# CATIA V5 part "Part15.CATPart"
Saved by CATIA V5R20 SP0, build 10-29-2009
Part number: bielle_2_hab
Bounding box of the stored display mesh (mm): x 0.1 to 0.15, y 0.877 to 2.164, z 2.08 to 2.712
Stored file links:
  D:\Dropbox\IAO_2012\IAO_2012_718_ccascaro\ccascaro\Part15.CATPart
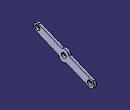
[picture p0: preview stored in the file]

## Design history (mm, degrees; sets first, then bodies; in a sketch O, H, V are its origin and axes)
Body1 (main body)
  Sketch1 on yz-plane, origin (0, 0, 0), H (0, 1, 0), V (0, 0, 1)
    point P1 (1.4759, 2.469)
    point P3 (1.4892, 2.3124)
    circle A1 centre (2.0719, 2.1705) radius 0.05
    arc A2 centre (2.073, 2.1711) radius 0.0914 from (2.1359, 2.2375) to (2.0105, 2.1045) cw
    line L1 (2.1359, 2.2375) -> (1.6294, 2.4448)
    line L2 (0.9853, 2.7085) -> (1.4759, 2.5077)
    point P10 (1.4759, 2.5077)
    arc A3 centre (1.5344, 2.4317) radius 0.0959 from (1.6294, 2.4448) to (1.4759, 2.5077) ccw
    line L3 (2.0102, 2.1048) -> (1.5666, 2.2879)
    point P13 (2.0102, 2.1048)
    line L4 (1.4111, 2.3495) -> (0.922, 2.5538)
    circle A4 centre (1.5199, 2.3994) radius 0.05
    circle A5 centre (0.9605, 2.6312) radius 0.05
    arc A6 centre (0.9606, 2.6283) radius 0.0839 from (0.922, 2.5538) to (0.9853, 2.7085) cw
    arc A7 centre (1.5045, 2.3583) radius 0.0939 from (1.5666, 2.2879) to (1.4111, 2.3495) cw
    coincidence: P10 L1, P13 A2
    tangency: A7 A4
  Pad1: profile Sketch1, direction (1, 0, 0), length 0.15, opposite side length -0.1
